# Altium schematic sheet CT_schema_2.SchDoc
size 271 x 273 mm
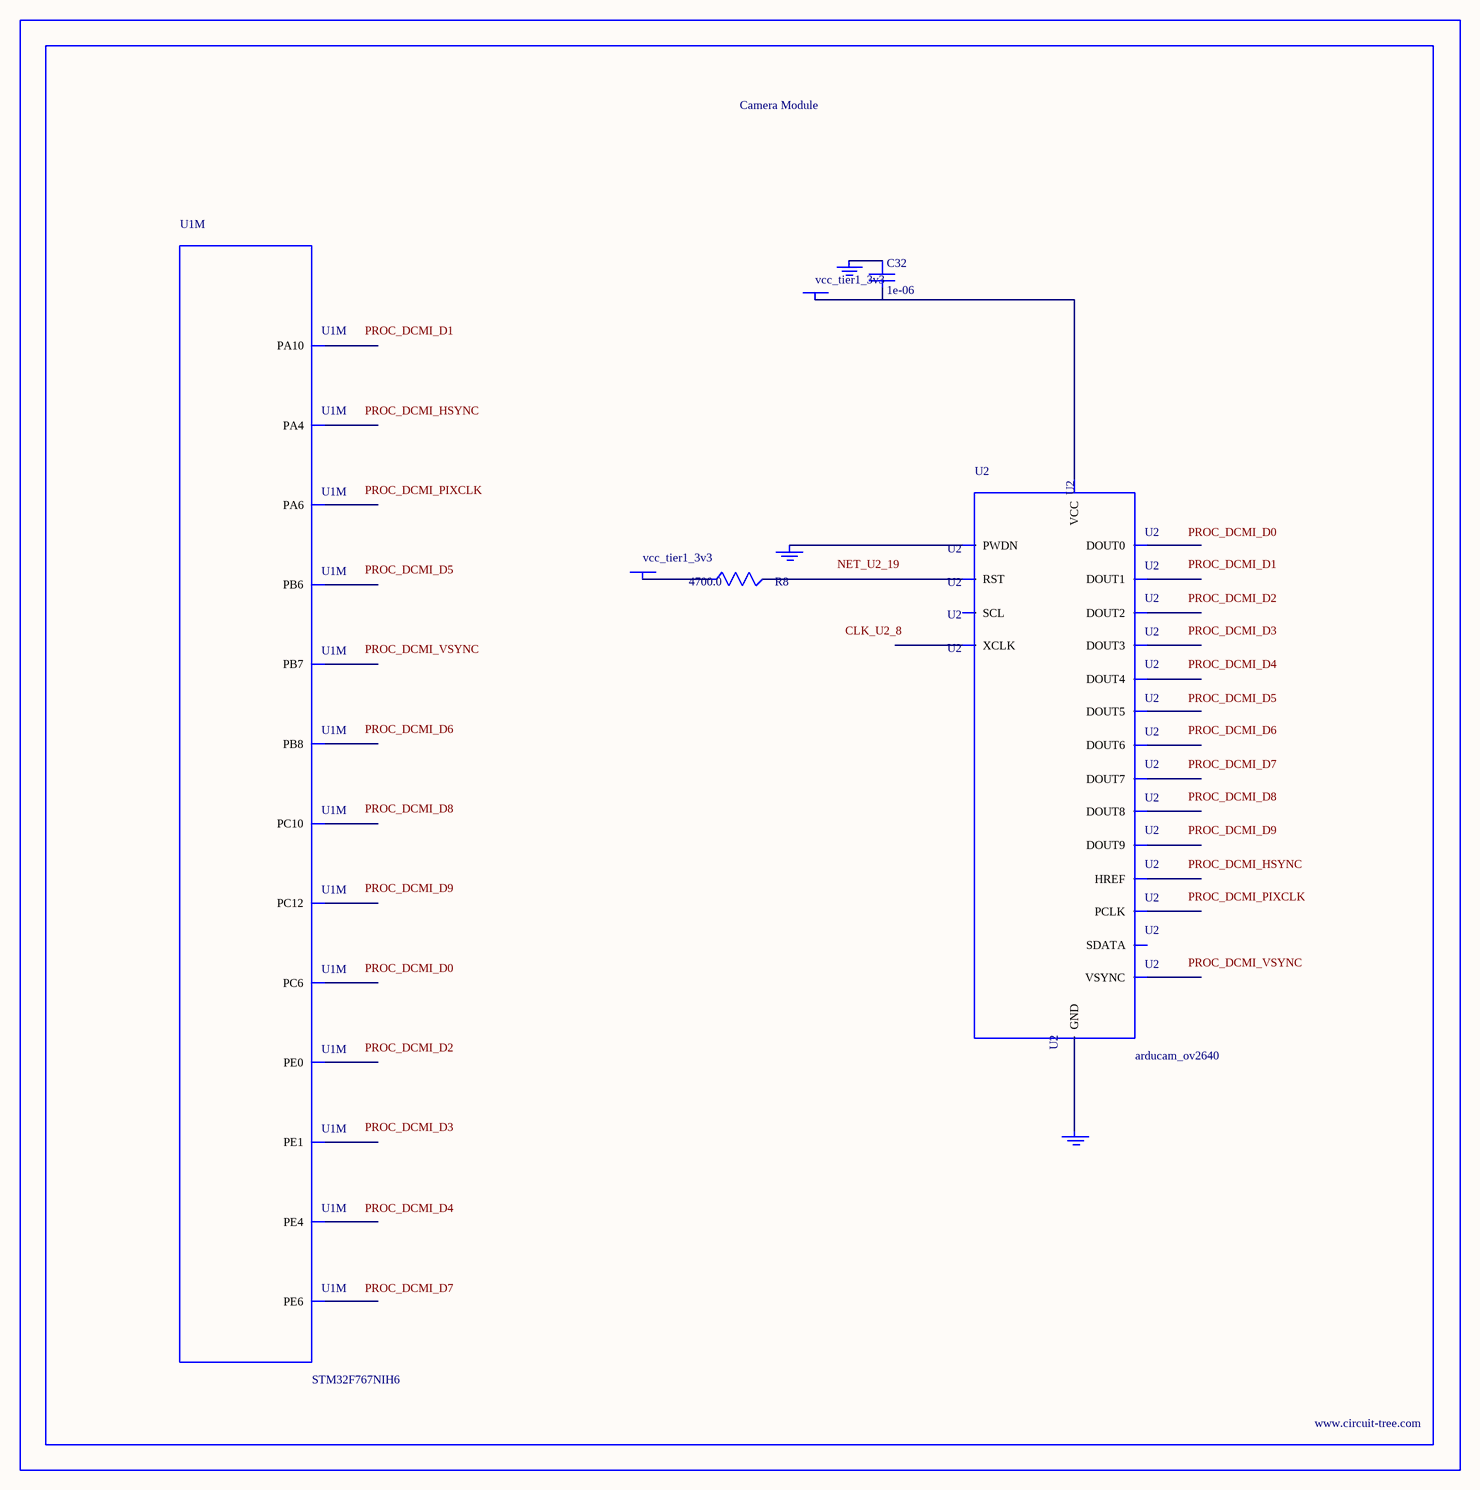
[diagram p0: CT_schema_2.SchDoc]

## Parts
BORDER1  (no value)
C32  1e-06  [C0603]
GND_INSTANCE_1_0  (no value)
GND_INSTANCE_1_1  (no value)
GND_INSTANCE_1_2  (no value)
POWER_INSTANCE_1_0  vcc_tier1_3v3
POWER_INSTANCE_1_1  vcc_tier1_3v3
R8  4700.0  [R0603]
U1  STM32F767NIH6  [TFBGA216]  (part M of 16)
U2  arducam_ov2640  [ARDUCAM]

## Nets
NetC32_1: C32.1 GND_INSTANCE_1_0.0(GND)
NetC32_2: C32.2 POWER_INSTANCE_1_0.0(PWR) U2.1(VCC)
NetGND_INSTANCE_1_1_0: GND_INSTANCE_1_1.0(GND) U2.20(PWDN)
NetGND_INSTANCE_1_2_0: GND_INSTANCE_1_2.0(GND) U2.2(GND)
NetPOWER_INSTANCE_1_1_0: POWER_INSTANCE_1_1.0(PWR) R8.1
NetR8_2: R8.2 U2.19(RST)

Not connected (* = marked no-connect by the designer): U1 A1(PE4) A5(PE1) A6(PE0) A7(PB8) A12(PC12) B2(PE6) B5(PB7) B6(PB6) B14(PC10) D15(PA10) H15(PC6) N4(PA4) P3(PA6); U2 3(SCL) 4(SDATA) 5(VSYNC) 6(HREF) 7(PCLK) 8(XCLK) 9(DOUT9) 10(DOUT8) 11(DOUT7) 12(DOUT6) 13(DOUT5) 14(DOUT4) 15(DOUT3) 16(DOUT2) 17(DOUT1) 18(DOUT0)

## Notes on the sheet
- Labels drawn without touching a wire or pin: CLK_U2_8, NET_U2_19, PROC_DCMI_D0, PROC_DCMI_D1, PROC_DCMI_D2, PROC_DCMI_D3, PROC_DCMI_D4, PROC_DCMI_D5, PROC_DCMI_D6, PROC_DCMI_D7, PROC_DCMI_D8, PROC_DCMI_D9, PROC_DCMI_HSYNC, PROC_DCMI_PIXCLK, PROC_DCMI_VSYNC

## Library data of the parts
BORDER1 = BORDER_PAGE1
C32 = C0603C105K3RACTU
GND_INSTANCE_1_0-GND_INSTANCE_1_2 = GND
POWER_INSTANCE_1_0 POWER_INSTANCE_1_1 = PWR
R8 = RC0603JR-074K7L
